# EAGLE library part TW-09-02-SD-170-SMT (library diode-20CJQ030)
SAMTEC Board Stacker TW-09-02-S-D-170-SM-(P/TR) 09: Number of pins 02: Lead Style -S: Plating Option -D: Row Option 170: Stacker Height -P : Pick and Place Pad -TR: Tape & Reel Packaging Please send any comments to: messi@users.sourceforge.net
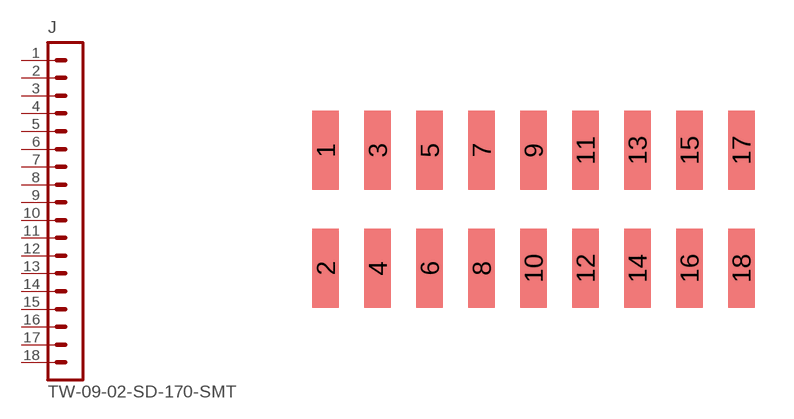
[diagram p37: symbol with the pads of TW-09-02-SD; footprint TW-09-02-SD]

Designator prefix J

## TW-09-02-SD-170-SMT  [TW-09-02-SD]
1  1  pas
2  2  pas
3  3  pas
4  4  pas
5  5  pas
6  6  pas
7  7  pas
8  8  pas
9  9  pas
10  10  pas
11  11  pas
12  12  pas
13  13  pas
14  14  pas
15  15  pas
16  16  pas
17  17  pas
18  18  pas

## Footprint TW-09-02-SD (pad centres in mm)
SAMTEC TW-09-02-SD-170-SMT Board Stacker Please send any comments to: messi@users.sourceforge.net
smd 1.02 x 3.025: 1 -8,2.272; 2 -8,-2.272; 3 -6,2.272; 4 -6,-2.272; 5 -4,2.272; 6 -4,-2.272; 7 -2,2.272; 8 -2,-2.272; 9 0,2.272; 10 0,-2.272; 11 2,2.272; 12 2,-2.272; 13 4,2.272; 14 4,-2.272; 15 6,2.272; 16 6,-2.272; 17 8,2.272; 18 8,-2.272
